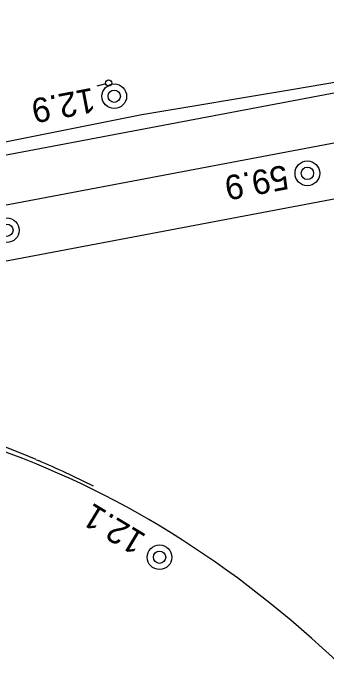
# Model space of a CAD drawing. Extents: x 6541740 to 6566395, y 5525066 to 5530361.
# Drawn here: x 6557569.6 to 6557595.3, y 5526197.9 to 5526251.7 of the extents above; entities that cross this region are included whole.
import ezdxf

# ---------------------------------------------------------------- set-up
doc = ezdxf.new("R2010")
doc.units = 0
for name, color, linetype in [('Domyślna', 7, 'Continuous'), ('TOR_PRZEK_P-komponent', 7, 'Continuous'), ('TOR_PS_T-rowy otwarte nieumocnione', 7, 'Continuous'), ('TOR_RAMKI-ramka+tabelka 1', 7, 'Continuous')]:
    doc.layers.add(name, color=color, linetype=linetype)

# ---------------------------------------------------------------- blocks, each defined once
blk = doc.blocks.new('4010_1')
at = {"layer": 'Domyślna'}
for radius in [0.75, 0.375]:
    blk.add_circle((0, 0), radius, dxfattribs=at)
blk = doc.blocks.new('4302_2')
at = {"layer": 'Domyślna'}
blk.add_line((0.246, -0.009), (0.996, -0.009), dxfattribs=at)
blk.add_circle((-0.004, -0.009), 0.25, dxfattribs=at)

msp = doc.modelspace()

# ---------------------------------------------------------------- linework, layer by layer
at = {"layer": 'TOR_PRZEK_P-komponent'}
for p, q in [((6557431.345, 5526213.97), (6557890.08, 5526300.925)), ((6557887.094, 5526296.236), (6557489.207, 5526220.816)), ((6557816.588, 5526278.292), (6557431.956, 5526205.384))]:
    msp.add_line(p, q, dxfattribs=at)
msp.add_ellipse((6557557.711, 5526118.36), major_axis=(-19.265, 100.033), ratio=0.728859, start_param=4.490747, end_param=6.139872, dxfattribs=at)
at = {"layer": 'TOR_PS_T-rowy otwarte nieumocnione'}
msp.add_line((6557571.51, 5526215.127), (6557571.68, 5526215.058), dxfattribs=at)
msp.add_line((6557571.51, 5526215.127), (6557571.68, 5526215.058), dxfattribs=at)
for points in [[(6557625.041, 5526251.188), (6557617.136, 5526249.701), (6557604.838, 5526247.519), (6557592.546, 5526245.407), (6557580.125, 5526243.331)], [(6557625.041, 5526251.188), (6557617.136, 5526249.701), (6557604.838, 5526247.519), (6557592.546, 5526245.407), (6557580.125, 5526243.331)], [(6557580.125, 5526243.331), (6557567.847, 5526240.889), (6557555.575, 5526238.232), (6557553.11, 5526237.736), (6557548.196, 5526236.791), (6557543.252, 5526235.96), (6557530.902, 5526234.065)], [(6557580.125, 5526243.331), (6557567.847, 5526240.889), (6557555.575, 5526238.232), (6557553.11, 5526237.736), (6557548.196, 5526236.791), (6557543.252, 5526235.96), (6557530.902, 5526234.065)]]:
    msp.add_lwpolyline(points, dxfattribs=at)
for centre, major_axis, ratio, start_param, end_param in [((6557557.403, 5526127.183), (17.715, -91.869), 0.728964, 2.677911, 2.821264), ((6557557.403, 5526127.183), (17.715, -91.869), 0.728964, 2.677911, 2.821264), ((6557554.53, 5526105.114), (22.085, -114.646), 0.728876, 2.629955, 2.683457), ((6557554.53, 5526105.114), (22.085, -114.646), 0.728876, 2.629955, 2.683457)]:
    msp.add_ellipse(centre, major_axis=major_axis, ratio=ratio, start_param=start_param, end_param=end_param, dxfattribs=at)

# ---------------------------------------------------------------- block references
at = {"layer": 'Domyślna', "xscale": 1.000000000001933, "yscale": 0.9999999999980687, "rotation": -164.7930514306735}
msp.add_blockref('4302_2', (6557577.423, 5526245.936), dxfattribs=at)
msp.add_blockref('4302_2', (6557577.423, 5526245.936), dxfattribs=at)
at = {"layer": 'TOR_RAMKI-ramka+tabelka 1', "xscale": 1.345963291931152, "yscale": 1.345963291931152}
for p in [(6557577.884, 5526244.864), (6557593.667, 5526238.556), (6557569.105, 5526233.9)]:
    msp.add_blockref('4010_1', p, dxfattribs=at)
at = {"layer": 'TOR_RAMKI-ramka+tabelka 1', "xscale": 1.345963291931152, "yscale": 1.3459632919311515, "rotation": -39.62712078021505}
msp.add_blockref('4010_1', (6557581.584, 5526207.144), dxfattribs=at)

# ---------------------------------------------------------------- texts
at = {"layer": 'TOR_RAMKI-ramka+tabelka 1'}
for s, rotation, p in [('12.9', 190.7691, (6557576.108, 5526245.571)), ('59.9', 190.7691, (6557591.891, 5526239.263)), ('12.1', 148.9459, (6557580.593, 5526208.939))]:
    msp.add_text(s, height=2, rotation=rotation, dxfattribs=at).set_placement(p)

doc.saveas('drawing.dxf')
